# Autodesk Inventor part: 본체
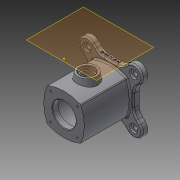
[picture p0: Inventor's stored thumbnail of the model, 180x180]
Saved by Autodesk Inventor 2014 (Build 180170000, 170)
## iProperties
Created: 2016-05
Part Number: 본체
Material: 일반
Document SubType Name: Modeling
Designer: Administrator
Density: 1 g/cm^3
Appearance: 기본값
Author: Administrator
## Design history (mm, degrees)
sketch "스케치2"
  geometry: L1 (-35.355, -35.355)-(35.355, -35.355); L2 (35.355, -35.355)-(35.355, 35.355); L3 (35.355, 35.355)-(-35.355, 35.355); L4 (-35.355, 35.355)-(-35.355, -35.355); L5 (-35.355, -35.355)-(35.355, 35.355); L6 (35.355, -35.355)-(-35.355, 35.355); L7 (0, -60.2)-(0, 60.2) reference; A1 r 85.579 centre (42.579, 0) between (-35.355, 35.355) and (-35.355, -35.355); A2 r 85.579 centre (0, 42.579) between (-35.355, -35.355) and (35.355, -35.355); A3 r 85.579 centre (-42.579, 0) between (35.355, -35.355) and (35.355, 35.355); A4 r 85.579 centre (0, -42.579) between (35.355, 35.355) and (-35.355, 35.355); 5 further points
  constraints: 12 end point, 12 point on circle, 4 centre point, 2 equal radius, 2 midpoint, 2 parallel, 1 horizontal, 1 perpendicular
  dimensions: "d4" = 100 distance of L1.end L3.end; "d5" = 45 deg angle of L7 L6; "d6" = 86 distance of point (0, -43) point (0, 43); "d7" = 86 distance of point (43, 0) point (-43, 0)
extrude "돌출1" new body sketch "스케치2" distance "d8" = 55; taper "d9" = 0 deg
sketch "스케치3"
  geometry: 2 further points
  constraints: 1 coincident
hole "구멍1" sketch "스케치3" at (0, 0) diameter "d10" = 50; stored, may be unused: countersink angle "d14" = 90 deg, drill point angle "d16" = 118 deg; dims "d11" = 6, "d12" = 70, "d13" = 43, "d15" = 8
sketch "스케치5"
  geometry: L1 (49, 55)-(49, 39); L2 (49, 39)-(71.821, 39); L3 (71.821, 39)-(69, 55); L4 (69, 55)-(49, 55); L5 (-22, 0)-(132, 0) reference; L6 (0, 43)-(110, 43) reference; L7 (0, -35.355)-(0, 35.355) reference; 1 further point
  constraints: 8 end point, 1 parallel, 1 perpendicular, 1 vertical
  dimensions: "d22" = 39 distance between parallel lines of L5 L2; "d23" = 55 distance between parallel lines of L5 L4; "d24" = 100 deg angle of L6 L3; "d25" = 49 distance between parallel lines of L7 L1; "d26" = 20 distance of L3.end L1.start
revolve "회전1" sketch "스케치5" stored, may be unused: angle "d27" = 90 deg
hole "구멍2" diameter "d30" = 25; stored, may be unused: countersink angle "d34" = 90 deg, drill point angle "d36" = 0 deg; dims "d28" = 10, "d29" = 10, "d31" = 6, "d32" = 30, "d33" = 8, "d35" = 8
sketch "스케치6" dims "d43" = 70
  geometry: L1 (0, 42.579)-(-49, 42.579); L2 (-49, 42.579)-(-49, 91.579); L3 (-49, 91.579)-(0, 91.579); L4 (0, 91.579)-(0, 42.579); L5 (0, 42.579)-(-67.637, 110.215); L6 (-74.953, 92.076)-(-49.497, 117.532); L7 (-49.497, 117.532)-(-23.544, 91.579); L8 (-23.544, 91.579)-(-49, 66.123); L9 (-49, 66.123)-(-74.953, 92.076); A1 r 25 centre (0, 42.579) between (0, 67.579) and (-25, 42.579) reference; 2 further points
  constraints: 18 end point, 5 point on line, 4 parallel, 3 perpendicular, 2 point on circle, 1 coincident, 1 horizontal, 3 other
  dimensions: "d37" = 45 deg angle of L4 L5; "d38" = 98 diameter of L2 L4; "d40" = 36 distance of L6.start L6.end; "d41" = 18 distance between parallel lines of L5 L7; "d44" = 18 distance from line of L6 point (-49.497, 92.076)
extrude "돌출4" join sketch "스케치6" distance "d47" = 12; taper "d48" = 0 deg
fillet "모깎기1"
fillet "모깎기2" dims "d49" = 25
hole "구멍3" diameter "d52" = 10; stored, may be unused: countersink angle "d56" = 90 deg, drill point angle "d58" = 0 deg; dims "d50" = 10, "d51" = 10, "d53" = 6, "d54" = 18, "d55" = 4, "d57" = 8
sketch "스케치7" dims "d60" = 40
  geometry: L1 (-30.866, 13.744)-(-36.77, 19.647) reference; L2 (0, -42.579)-(-49.497, 6.919); C1 r 25 at (0, -42.579) reference; A1 r 18 centre (-49.497, 6.919) between (-36.77, 19.647) and (-62.225, -5.809) reference; 1 further point
  constraints: 2 end point, 1 coincident, 1 parallel, 1 point on line, 3 other
hole "구멍4" sketch "스케치7" at (-28.284, -14.294) diameter "d61" = 3.242; stored, may be unused: countersink angle "d65" = 90 deg, drill point angle "d67" = 118 deg; dims "d62" = 7, "d63" = 18, "d64" = 4, "d66" = 10
sketch "스케치8"
  geometry: L1 (0, 0)-(-28.284, 28.284); L2 (0, -94.496)-(0, 94.496) reference; C1 r 25 at (0, 0) reference
  constraints: 2 end point
  dimensions: "d68" = 40 distance of L1.start L1.end; "d69" = 45 deg angle of L2 L1
hole "구멍5" sketch "스케치8" at (-28.284, 28.284) diameter "d70" = 3.242; stored, may be unused: countersink angle "d74" = 90 deg, drill point angle "d76" = 118 deg; dims "d71" = 7, "d72" = 18, "d73" = 4, "d75" = 10
chamfer "모따기1" distance "d80" = 1; stored, may be unused: second distance "d81" = 2, angle "d82" = 45 deg
fillet "모깎기3" dims "d83" = 3
fillet "모깎기4" dims "d84" = 3
fillet "모깎기5" dims "d85" = 3
fillet "모깎기6" dims "d86" = 3
node "작업 평면3"
sketch "스케치9"
  geometry: L1 (37.122, 80.019)-(54.721, 80.019); L2 (54.721, 80.019)-(54.721, 24.198); L3 (54.721, 24.198)-(37.122, 24.198); L4 (37.122, 24.198)-(37.122, 80.019); 1 further point
  constraints: 2 other
node "솔리드1"
mirror "대칭1"
mirror "대칭2"
mirror "대칭3"
pattern_circular "원형 패턴1" dims angle "d78" = 360 deg
other parameters: "d87" = 102.25
